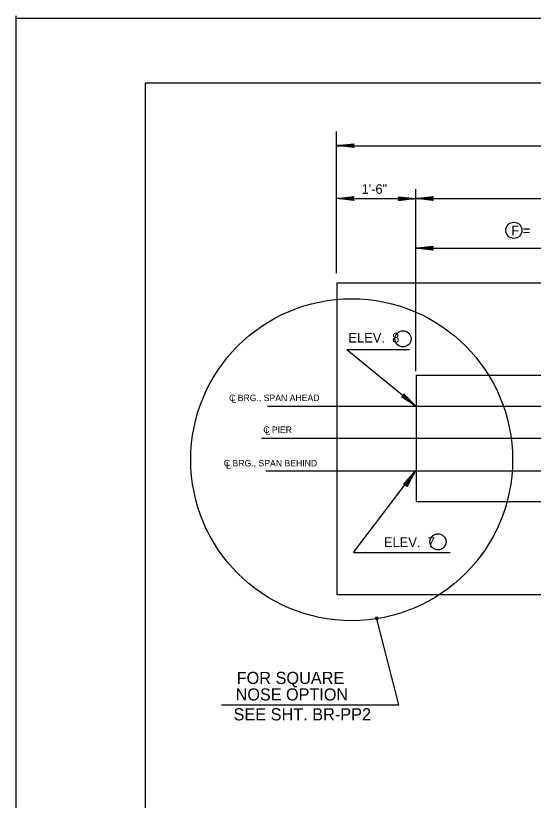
# Model space of a CAD drawing. Extents: x 1.6 to 6.29, y 2.8 to 7.08.
# Drawn here: x 2.391 to 3.058, y 6.075 to 7.085 of the extents above; entities that cross this region are included whole.
import ezdxf

# ---------------------------------------------------------------- set-up
doc = ezdxf.new("R2010")
doc.units = 0
doc.layers.add('Level 1', color=7, linetype='Continuous')
doc.layers.add('Level 5', color=7, linetype='Continuous')

msp = doc.modelspace()

# ---------------------------------------------------------------- linework, layer by layer
at = {"layer": 'Level 1'}
for p, q in [((2.3914, 7.0849), (2.3914, 4.6712)), ((6.2614, 7.0813), (2.3914, 7.0813)), ((6.1848, 6.998), (2.5581, 6.998)), ((2.5581, 6.998), (2.5581, 4.758)), ((2.8043, 6.7538), (2.8043, 6.9359)), ((2.8048, 6.9177), (2.8268, 6.9202)), ((2.8268, 6.9177), (2.8048, 6.9177)), ((2.8268, 6.9153), (2.8048, 6.9177)), ((2.8052, 6.9176), (3.6071, 6.9176)), ((2.8103, 6.9181), (2.8078, 6.9178)), ((2.8078, 6.9178), (2.8253, 6.9179)), ((2.8085, 6.9175), (2.8103, 6.9181)), ((2.8182, 6.9172), (2.8085, 6.9175)), ((2.8262, 6.9156), (2.8098, 6.9174)), ((2.8262, 6.9156), (2.8098, 6.9174)), ((2.8262, 6.9158), (2.8098, 6.9174)), ((2.8263, 6.9161), (2.8099, 6.9177)), ((2.8262, 6.9158), (2.8099, 6.9176)), ((2.8262, 6.9198), (2.8108, 6.9181)), ((2.8262, 6.9196), (2.8108, 6.9179)), ((2.8263, 6.9194), (2.811, 6.9177)), ((2.8263, 6.9191), (2.811, 6.9174)), ((2.8142, 6.9174), (2.8256, 6.9187)), ((2.8256, 6.9182), (2.8142, 6.9174)), ((2.8153, 6.9173), (2.8153, 6.9175)), ((2.8153, 6.9175), (2.8174, 6.9174)), ((2.8253, 6.9174), (2.8153, 6.9173)), ((2.8174, 6.9174), (2.8253, 6.9173)), ((2.8257, 6.9165), (2.8182, 6.9172)), ((2.8253, 6.9173), (2.8188, 6.9172)), ((2.8188, 6.9172), (2.8256, 6.9168)), ((2.8253, 6.9179), (2.82, 6.9182)), ((2.82, 6.9182), (2.8256, 6.9182)), ((2.8256, 6.9168), (2.8209, 6.9167)), ((2.8209, 6.9167), (2.8257, 6.9165)), ((2.8252, 6.9172), (2.8245, 6.9168)), ((2.8245, 6.9168), (2.825, 6.9162)), ((2.825, 6.9162), (2.8254, 6.9177)), ((2.8256, 6.9187), (2.8252, 6.9174)), ((2.8252, 6.9174), (2.8261, 6.9159)), ((2.8256, 6.9162), (2.8252, 6.9172)), ((2.8254, 6.9177), (2.8258, 6.9187)), ((2.8268, 6.9202), (2.8256, 6.9177)), ((2.8256, 6.9177), (2.8268, 6.9153)), ((2.8261, 6.9159), (2.8256, 6.9162)), ((2.8258, 6.9187), (2.8262, 6.9198)), ((2.9064, 6.8275), (2.9064, 6.8618)), ((2.8046, 6.8495), (2.8266, 6.8521)), ((2.8266, 6.8495), (2.8046, 6.8495)), ((2.8266, 6.8471), (2.8046, 6.8495)), ((2.8102, 6.8499), (2.8077, 6.8497)), ((2.8077, 6.8497), (2.8251, 6.8497)), ((2.8083, 6.8494), (2.8102, 6.8499)), ((2.8181, 6.849), (2.8083, 6.8494)), ((2.8092, 6.8495), (3.6028, 6.8495)), ((2.8261, 6.8473), (2.8097, 6.8492)), ((2.8261, 6.8474), (2.8097, 6.8492)), ((2.8261, 6.8475), (2.8097, 6.8492)), ((2.8262, 6.8479), (2.8098, 6.8496)), ((2.8261, 6.8477), (2.8098, 6.8495)), ((2.8261, 6.8516), (2.8108, 6.8499)), ((2.8261, 6.8514), (2.8108, 6.8497)), ((2.8262, 6.8511), (2.8108, 6.8495)), ((2.8262, 6.8508), (2.8108, 6.8492)), ((2.8141, 6.8492), (2.8255, 6.8505)), ((2.8254, 6.8501), (2.8141, 6.8492)), ((2.8152, 6.8492), (2.8152, 6.8494)), ((2.8152, 6.8494), (2.8173, 6.8492)), ((2.8251, 6.8492), (2.8152, 6.8492)), ((2.8173, 6.8492), (2.8251, 6.8492)), ((2.8256, 6.8485), (2.8181, 6.849)), ((2.8251, 6.8492), (2.8188, 6.849)), ((2.8188, 6.849), (2.8254, 6.8488)), ((2.8251, 6.8497), (2.8198, 6.8501)), ((2.8198, 6.8501), (2.8254, 6.8501)), ((2.8254, 6.8488), (2.8208, 6.8487)), ((2.8208, 6.8487), (2.8256, 6.8485)), ((2.825, 6.849), (2.8243, 6.8487)), ((2.8243, 6.8487), (2.8247, 6.8482)), ((2.8247, 6.8482), (2.8252, 6.8496)), ((2.8255, 6.8505), (2.825, 6.8492)), ((2.825, 6.8492), (2.8259, 6.8478)), ((2.8255, 6.8483), (2.825, 6.849)), ((2.8252, 6.8496), (2.8256, 6.8505)), ((2.8266, 6.8521), (2.8255, 6.8495)), ((2.8255, 6.8495), (2.8266, 6.8471)), ((2.8259, 6.8478), (2.8255, 6.8483)), ((2.8256, 6.8505), (2.8261, 6.8516)), ((2.8841, 6.8518), (2.9062, 6.8495)), ((2.8852, 6.8495), (2.8841, 6.8518)), ((2.8841, 6.8495), (2.9062, 6.8495)), ((2.9062, 6.8495), (2.8841, 6.8471)), ((2.8841, 6.8471), (2.8852, 6.8495)), ((2.8844, 6.8516), (2.901, 6.8497)), ((2.8844, 6.8515), (2.901, 6.8497)), ((2.8844, 6.8514), (2.901, 6.8496)), ((2.8844, 6.8511), (2.901, 6.8494)), ((2.8844, 6.8483), (2.8998, 6.8497)), ((2.8844, 6.8479), (2.8998, 6.8495)), ((2.8844, 6.8477), (2.8998, 6.8492)), ((2.8845, 6.8517), (2.901, 6.8498)), ((2.8845, 6.8473), (2.8998, 6.8492)), ((2.8849, 6.8486), (2.8845, 6.8474)), ((2.8856, 6.8497), (2.8846, 6.8512)), ((2.8846, 6.8512), (2.8851, 6.8508)), ((2.8853, 6.8495), (2.8849, 6.8486)), ((2.8897, 6.8504), (2.885, 6.8507)), ((2.885, 6.8507), (2.8927, 6.8501)), ((2.8851, 6.8508), (2.8856, 6.8501)), ((2.8964, 6.8497), (2.8851, 6.8486)), ((2.8851, 6.8486), (2.8856, 6.8497)), ((2.8852, 6.8502), (2.8897, 6.8504)), ((2.8918, 6.8501), (2.8852, 6.8502)), ((2.8852, 6.849), (2.8964, 6.8497)), ((2.8907, 6.849), (2.8852, 6.849)), ((2.8857, 6.851), (2.8853, 6.8495)), ((2.8854, 6.8499), (2.8918, 6.8501)), ((2.8854, 6.8497), (2.8953, 6.8499)), ((2.8934, 6.8497), (2.8854, 6.8499)), ((2.9032, 6.8494), (2.8854, 6.8492)), ((2.8854, 6.8492), (2.8907, 6.849)), ((2.8856, 6.8501), (2.8861, 6.8503)), ((2.8861, 6.8503), (2.8857, 6.851)), ((2.8927, 6.8501), (2.9024, 6.8497)), ((2.8952, 6.8497), (2.8934, 6.8497)), ((2.8953, 6.8499), (2.8952, 6.8497)), ((2.9024, 6.8497), (2.9004, 6.8492)), ((2.9004, 6.8492), (2.9032, 6.8494)), ((2.9064, 6.8495), (2.9284, 6.8521)), ((2.9284, 6.8495), (2.9064, 6.8495)), ((2.9284, 6.8471), (2.9064, 6.8495)), ((2.9121, 6.8499), (2.9095, 6.8497)), ((2.9095, 6.8497), (2.927, 6.8497)), ((2.9102, 6.8494), (2.9121, 6.8499)), ((2.9199, 6.849), (2.9102, 6.8494)), ((2.9279, 6.8473), (2.9117, 6.8492)), ((2.9279, 6.8474), (2.9117, 6.8492)), ((2.9279, 6.8475), (2.9117, 6.8492)), ((2.928, 6.8479), (2.9118, 6.8496)), ((2.9279, 6.8477), (2.9118, 6.8495)), ((2.9279, 6.8516), (2.9127, 6.8499)), ((2.9279, 6.8514), (2.9127, 6.8497)), ((2.928, 6.8511), (2.9127, 6.8495)), ((2.928, 6.8508), (2.9127, 6.8492)), ((2.916, 6.8492), (2.9273, 6.8505)), ((2.9272, 6.8501), (2.916, 6.8492)), ((2.9172, 6.8492), (2.9172, 6.8494)), ((2.9172, 6.8494), (2.9191, 6.8492)), ((2.927, 6.8492), (2.9172, 6.8492)), ((2.9191, 6.8492), (2.927, 6.8492)), ((2.9274, 6.8485), (2.9199, 6.849)), ((2.927, 6.8492), (2.9207, 6.849)), ((2.9207, 6.849), (2.9272, 6.8488)), ((2.927, 6.8497), (2.9217, 6.8501)), ((2.9217, 6.8501), (2.9272, 6.8501)), ((2.9272, 6.8488), (2.9227, 6.8487)), ((2.9227, 6.8487), (2.9274, 6.8485)), ((2.9269, 6.849), (2.9263, 6.8487)), ((2.9263, 6.8487), (2.9267, 6.8482)), ((2.9267, 6.8482), (2.9271, 6.8496)), ((2.9273, 6.8505), (2.9269, 6.8492)), ((2.9269, 6.8492), (2.9278, 6.8478)), ((2.9273, 6.8483), (2.9269, 6.849)), ((2.9271, 6.8496), (2.9275, 6.8505)), ((2.9284, 6.8521), (2.9273, 6.8495)), ((2.9273, 6.8495), (2.9284, 6.8471)), ((2.9278, 6.8478), (2.9273, 6.8483)), ((2.9275, 6.8505), (2.9279, 6.8516)), ((2.9064, 6.7391), (2.9064, 6.8418)), ((2.9064, 6.6277), (2.9064, 6.7858)), ((2.9064, 6.7858), (3.5077, 6.7858)), ((2.9065, 6.7858), (2.9286, 6.7883)), ((2.9286, 6.7858), (2.9065, 6.7858)), ((2.9286, 6.7834), (2.9065, 6.7858)), ((2.9122, 6.7862), (2.9095, 6.786)), ((2.9095, 6.786), (2.9271, 6.7861)), ((2.9102, 6.7857), (2.9122, 6.7862)), ((2.92, 6.7852), (2.9102, 6.7857)), ((2.9281, 6.7837), (2.9117, 6.7856)), ((2.9281, 6.7838), (2.9117, 6.7856)), ((2.9281, 6.7837), (2.9117, 6.7855)), ((2.9282, 6.7842), (2.9118, 6.7859)), ((2.9281, 6.7839), (2.9118, 6.7858)), ((2.9281, 6.7879), (2.9127, 6.7862)), ((2.9281, 6.7877), (2.9127, 6.7861)), ((2.9282, 6.7875), (2.9128, 6.7858)), ((2.9282, 6.7872), (2.9128, 6.7856)), ((2.9161, 6.7856), (2.9274, 6.7868)), ((2.9273, 6.7864), (2.9161, 6.7856)), ((2.9173, 6.7854), (2.9173, 6.7857)), ((2.9173, 6.7857), (2.9192, 6.7856)), ((2.9271, 6.7856), (2.9173, 6.7854)), ((2.9192, 6.7856), (2.9271, 6.7854)), ((2.9275, 6.7847), (2.92, 6.7852)), ((2.9271, 6.7854), (2.9207, 6.7852)), ((2.9207, 6.7852), (2.9273, 6.7851)), ((2.9271, 6.7861), (2.9219, 6.7864)), ((2.9219, 6.7864), (2.9273, 6.7864)), ((2.9273, 6.7851), (2.9227, 6.7849)), ((2.9227, 6.7849), (2.9275, 6.7847)), ((2.927, 6.7852), (2.9264, 6.785)), ((2.9264, 6.785), (2.9268, 6.7843)), ((2.9268, 6.7843), (2.9272, 6.7859)), ((2.9274, 6.7868), (2.927, 6.7856)), ((2.927, 6.7856), (2.9279, 6.7841)), ((2.9274, 6.7844), (2.927, 6.7852)), ((2.9272, 6.7859), (2.9276, 6.7868)), ((2.9286, 6.7883), (2.9274, 6.7858)), ((2.9274, 6.7858), (2.9286, 6.7834)), ((2.9279, 6.7841), (2.9274, 6.7844)), ((2.9276, 6.7868), (2.9281, 6.7879)), ((2.8053, 6.3399), (2.8053, 6.7412)), ((2.8053, 6.7412), (3.6078, 6.7412)), ((2.8176, 6.6552), (2.8982, 6.6552)), ((2.8176, 6.6552), (2.9027, 6.5861)), ((2.9066, 6.6223), (2.9066, 6.4597)), ((2.9066, 6.6223), (3.4276, 6.6223)), ((2.8878, 6.5947), (2.8902, 6.5958)), ((2.9063, 6.5823), (2.8878, 6.5947)), ((2.8894, 6.5953), (2.8884, 6.5947)), ((2.8884, 6.5947), (2.9012, 6.5862)), ((2.8885, 6.5948), (2.9013, 6.5863)), ((2.8886, 6.5951), (2.9014, 6.5864)), ((2.8887, 6.5953), (2.9017, 6.5867)), ((2.8893, 6.5966), (2.9063, 6.5823)), ((2.8894, 6.5952), (2.8907, 6.5957)), ((2.8903, 6.5957), (2.8894, 6.5953)), ((2.899, 6.5887), (2.8894, 6.5952)), ((2.894, 6.5918), (2.8899, 6.5953)), ((2.8899, 6.5953), (2.899, 6.5887)), ((2.8902, 6.5958), (2.8908, 6.5985)), ((2.8916, 6.5966), (2.8903, 6.5957)), ((2.9038, 6.5841), (2.8903, 6.5955)), ((2.8903, 6.5955), (2.894, 6.5918)), ((2.8905, 6.5958), (2.8983, 6.5897)), ((2.8907, 6.5977), (2.9023, 6.5858)), ((2.8907, 6.5976), (2.9022, 6.5857)), ((2.8907, 6.5957), (2.8908, 6.5975)), ((2.8944, 6.5935), (2.8907, 6.5968)), ((2.8907, 6.5968), (2.8963, 6.5916)), ((2.8958, 6.592), (2.8907, 6.5963)), ((2.8907, 6.5963), (2.8944, 6.5935)), ((2.8967, 6.5908), (2.8907, 6.5959)), ((2.8907, 6.5959), (2.8958, 6.592)), ((2.8908, 6.5985), (2.9063, 6.5823)), ((2.8908, 6.5978), (2.9024, 6.5858)), ((2.8908, 6.5975), (2.891, 6.5969)), ((2.891, 6.5969), (2.8908, 6.596)), ((2.8908, 6.596), (2.8913, 6.5958)), ((2.891, 6.598), (2.9024, 6.5861)), ((2.891, 6.598), (2.9024, 6.586)), ((2.8913, 6.5958), (2.8916, 6.5966)), ((2.7154, 6.5824), (3.6545, 6.5824)), ((2.8963, 6.5916), (2.9035, 6.585)), ((2.8981, 6.5894), (2.8967, 6.5908)), ((2.8983, 6.5897), (2.8981, 6.5894)), ((2.9035, 6.585), (2.9017, 6.5858)), ((2.9017, 6.5858), (2.9038, 6.5841)), ((3.2051, 6.5408), (2.7077, 6.5408)), ((2.7135, 6.4992), (3.6501, 6.4992)), ((2.8262, 6.3942), (2.9061, 6.4992)), ((2.8907, 6.4816), (2.9057, 6.4985)), ((2.8912, 6.4826), (2.9061, 6.4992)), ((2.8913, 6.4819), (2.9022, 6.4943)), ((2.8913, 6.4818), (2.9022, 6.4943)), ((2.8913, 6.4817), (2.9024, 6.4943)), ((2.8914, 6.4817), (2.9024, 6.4942)), ((2.8917, 6.4815), (2.9026, 6.494)), ((2.8918, 6.4828), (2.9027, 6.4952)), ((2.8918, 6.4827), (2.9028, 6.4952)), ((2.8918, 6.4826), (2.903, 6.4952)), ((2.892, 6.4826), (2.903, 6.495)), ((2.8922, 6.4825), (2.9031, 6.4948)), ((2.8928, 6.4802), (2.9057, 6.4985)), ((2.8933, 6.4812), (2.9061, 6.4992)), ((2.9039, 6.4958), (2.8938, 6.4814)), ((2.8942, 6.4798), (2.9017, 6.4933)), ((2.9044, 6.4967), (2.8944, 6.4822)), ((2.8944, 6.4798), (2.9018, 6.4932)), ((2.8945, 6.4817), (2.9003, 6.4915)), ((2.8947, 6.4805), (2.9022, 6.4943)), ((2.8947, 6.4796), (2.9021, 6.4932)), ((2.8947, 6.4794), (2.9022, 6.4931)), ((2.9003, 6.4915), (2.8947, 6.4814)), ((2.9057, 6.4985), (2.8948, 6.4788)), ((2.8948, 6.4805), (2.9023, 6.4941)), ((2.8951, 6.4804), (2.9026, 6.4939)), ((2.8952, 6.4802), (2.9027, 6.4937)), ((2.9061, 6.4992), (2.8953, 6.4798)), ((2.8973, 6.4877), (2.9032, 6.4955)), ((2.8977, 6.4886), (2.9038, 6.4963)), ((2.9024, 6.4934), (2.9039, 6.4958)), ((2.9032, 6.4955), (2.9024, 6.4934)), ((2.9031, 6.4944), (2.9044, 6.4967)), ((2.9038, 6.4963), (2.9031, 6.4944)), ((2.8934, 6.4813), (2.8907, 6.4816)), ((2.8939, 6.4821), (2.8912, 6.4826)), ((2.8918, 6.4817), (2.8922, 6.482)), ((2.8935, 6.4816), (2.8918, 6.4817)), ((2.8922, 6.4826), (2.8928, 6.4828)), ((2.8942, 6.4826), (2.8922, 6.4826)), ((2.8922, 6.482), (2.8932, 6.4819)), ((2.8924, 6.4817), (2.8973, 6.4877)), ((2.8954, 6.4856), (2.8924, 6.4817)), ((2.8933, 6.4825), (2.8925, 6.4825)), ((2.8925, 6.4825), (2.8937, 6.4813)), ((2.8928, 6.4828), (2.8937, 6.4828)), ((2.8929, 6.4826), (2.8977, 6.4886)), ((2.8968, 6.4871), (2.8929, 6.4817)), ((2.896, 6.4864), (2.8929, 6.4826)), ((2.8929, 6.4817), (2.8954, 6.4856)), ((2.8937, 6.4833), (2.8931, 6.4833)), ((2.8931, 6.4833), (2.8942, 6.4822)), ((2.8932, 6.4819), (2.8933, 6.4825)), ((2.8979, 6.4882), (2.8933, 6.4817)), ((2.8933, 6.4817), (2.8968, 6.4871)), ((2.8934, 6.4816), (2.899, 6.4898)), ((2.8973, 6.4878), (2.8934, 6.4826)), ((2.8934, 6.4826), (2.896, 6.4864)), ((2.8942, 6.4806), (2.8935, 6.4816)), ((2.8937, 6.4828), (2.8937, 6.4833)), ((2.8985, 6.489), (2.8938, 6.4827)), ((2.8938, 6.4827), (2.8973, 6.4878)), ((2.8938, 6.4814), (2.8971, 6.4854)), ((2.8939, 6.4826), (2.8995, 6.4907)), ((2.8939, 6.4811), (2.8998, 6.4905)), ((2.8971, 6.4854), (2.8939, 6.4811)), ((2.8953, 6.4798), (2.8939, 6.4821)), ((2.8998, 6.4905), (2.8942, 6.4806)), ((2.8947, 6.4814), (2.8942, 6.4826)), ((2.8942, 6.4822), (2.8947, 6.4813)), ((2.8944, 6.4822), (2.8975, 6.4863)), ((2.8975, 6.4863), (2.8945, 6.4817)), ((2.8992, 6.4896), (2.8979, 6.4882)), ((2.8997, 6.4905), (2.8985, 6.489)), ((2.899, 6.4898), (2.8992, 6.4896)), ((2.8995, 6.4907), (2.8997, 6.4905)), ((2.8948, 6.4788), (2.8934, 6.4813)), ((2.8937, 6.4813), (2.8942, 6.4805)), ((2.8942, 6.4805), (2.8947, 6.4795)), ((2.8947, 6.4813), (2.8952, 6.4804)), ((2.9066, 6.4597), (3.4333, 6.4597)), ((2.8262, 6.3942), (2.9506, 6.3942)), ((3.6078, 6.3399), (2.8053, 6.3399)), ((2.8543, 6.3095), (2.8576, 6.3099)), ((2.8544, 6.3101), (2.8575, 6.3103)), ((2.8544, 6.3098), (2.8562, 6.3102)), ((2.8564, 6.3081), (2.8544, 6.3101)), ((2.857, 6.3083), (2.8544, 6.3098)), ((2.8546, 6.3103), (2.8558, 6.3111)), ((2.8547, 6.3104), (2.8546, 6.3087)), ((2.8559, 6.3097), (2.8546, 6.3103)), ((2.8567, 6.311), (2.8547, 6.3104)), ((2.8576, 6.3099), (2.8547, 6.3104)), ((2.8547, 6.3104), (2.8576, 6.3092)), ((2.8548, 6.3104), (2.8547, 6.3087)), ((2.8547, 6.3099), (2.8573, 6.3095)), ((2.8547, 6.3098), (2.8573, 6.3093)), ((2.8549, 6.3104), (2.8548, 6.3087)), ((2.8548, 6.3104), (2.8573, 6.3101)), ((2.8548, 6.3103), (2.8573, 6.3098)), ((2.8548, 6.3103), (2.8573, 6.31)), ((2.8548, 6.3102), (2.8573, 6.3097)), ((2.8548, 6.31), (2.8573, 6.3096)), ((2.8563, 6.3111), (2.8549, 6.3083)), ((2.8549, 6.3083), (2.8554, 6.3111)), ((2.8549, 6.3107), (2.8573, 6.3103)), ((2.855, 6.3104), (2.8549, 6.3087)), ((2.8552, 6.3104), (2.855, 6.3087)), ((2.8552, 6.3104), (2.8552, 6.3087)), ((2.8554, 6.3111), (2.8564, 6.3081)), ((2.8554, 6.3081), (2.8567, 6.311)), ((2.8555, 6.3104), (2.8554, 6.3087)), ((2.8575, 6.3103), (2.8554, 6.3081)), ((2.8556, 6.3104), (2.8555, 6.3087)), ((2.8557, 6.3104), (2.8556, 6.3087)), ((2.8558, 6.3104), (2.8557, 6.3087)), ((2.8558, 6.3111), (2.8559, 6.3098)), ((2.8559, 6.3104), (2.8558, 6.3087)), ((2.8559, 6.3081), (2.8563, 6.3111)), ((2.8567, 6.311), (2.8559, 6.3097)), ((2.8571, 6.3107), (2.8559, 6.3081)), ((2.856, 6.3104), (2.8559, 6.3087)), ((2.8559, 6.3098), (2.857, 6.3083)), ((2.8562, 6.3104), (2.856, 6.3087)), ((2.8562, 6.3102), (2.8571, 6.3107)), ((2.8563, 6.3103), (2.8562, 6.3086)), ((2.8566, 6.3103), (2.8563, 6.3086)), ((2.8567, 6.3103), (2.8566, 6.3086)), ((2.8567, 6.3103), (2.8566, 6.3086)), ((2.8575, 6.3103), (2.8567, 6.311)), ((2.8567, 6.3103), (2.8567, 6.3086)), ((2.8568, 6.3103), (2.8567, 6.3086)), ((2.857, 6.3103), (2.8568, 6.3086)), ((2.8571, 6.3103), (2.857, 6.3086)), ((2.8571, 6.3083), (2.8571, 6.3107)), ((2.8572, 6.3103), (2.8571, 6.3086)), ((2.8573, 6.3103), (2.8572, 6.3086)), ((2.8575, 6.3103), (2.8573, 6.3086)), ((2.8576, 6.3092), (2.8575, 6.3103)), ((2.8576, 6.3092), (2.8546, 6.3087)), ((2.8546, 6.3088), (2.8571, 6.3084)), ((2.8546, 6.3087), (2.8571, 6.3083)), ((2.8546, 6.3087), (2.8559, 6.3081)), ((2.8547, 6.3097), (2.8572, 6.3092)), ((2.8547, 6.3096), (2.8572, 6.3091)), ((2.8547, 6.3093), (2.8572, 6.3088)), ((2.8547, 6.3091), (2.8572, 6.3087)), ((2.8547, 6.309), (2.8571, 6.3086)), ((2.8547, 6.3088), (2.8571, 6.3085)), ((2.8549, 6.3083), (2.8559, 6.3097)), ((2.8573, 6.3086), (2.8549, 6.3083)), ((2.8559, 6.3097), (2.8573, 6.3086)), ((2.8559, 6.3081), (2.8571, 6.3083)), ((2.8846, 6.1984), (2.8563, 6.309)), ((2.8571, 6.3083), (2.8576, 6.3092)), ((2.6561, 6.1984), (2.8846, 6.1984))]:
    msp.add_line(p, q, dxfattribs=at)
for centre, radius in [((3.0325, 6.8087), 0.0104), ((2.8238, 6.5136), 0.2071), ((2.8899, 6.6691), 0.0104), ((2.9348, 6.408), 0.0104), ((2.856, 6.3095), 0.00164)]:
    msp.add_circle(centre, radius, dxfattribs=at)

# ---------------------------------------------------------------- texts
for s, height, p in [('1\'-6"', 0.01233, (2.8366, 6.8557)), ('C BRG., SPAN AHEAD', 0.008333, (2.666, 6.589)), ('L', 0.00833, (2.6692, 6.5869)), ('C PIER', 0.00825, (2.7101, 6.5481)), ('L', 0.00825, (2.7129, 6.5457)), ('C BRG., SPAN BEHIND', 0.008333, (2.6593, 6.505)), ('L', 0.00825, (2.6622, 6.5022))]:
    msp.add_text(s, height=height, dxfattribs=at).set_placement(p)
at = {"layer": 'Level 5'}
for s, height, p in [('F =      ', 0.0125, (3.0292, 6.8022)), ('ELEV.  8', 0.01242, (2.8196, 6.6644)), ('ELEV.  7', 0.01242, (2.8653, 6.4012)), ('FOR SQUARE', 0.01567, (2.6758, 6.225)), ('NOSE OPTION', 0.015583, (2.6745, 6.2038)), ('SEE SHT. BR-PP2', 0.015666, (2.6718, 6.1782))]:
    msp.add_text(s, height=height, dxfattribs=at).set_placement(p)

doc.saveas('drawing.dxf')
